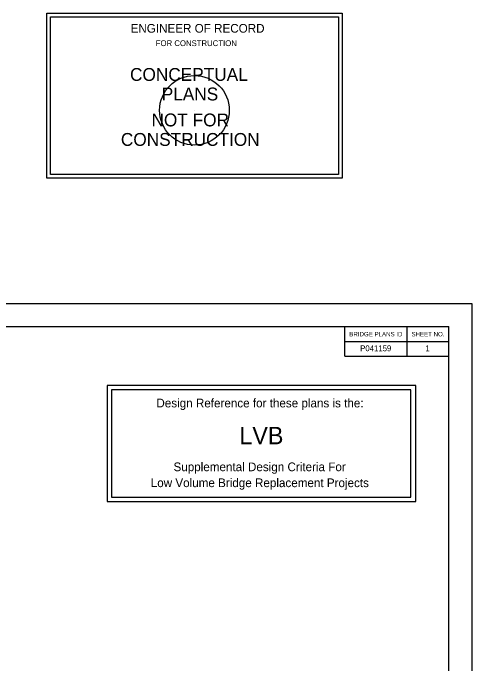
# Model space of a CAD drawing. Extents: x 0 to 4.05, y -2.5 to 2.32.
# Drawn here: x 2.177 to 3, y -1.314 to -0.145 of the extents above; entities that cross this region are included whole.
import ezdxf

# ---------------------------------------------------------------- set-up
doc = ezdxf.new("R2010")
doc.units = 0
for name, color, linetype in [('BR_AUTO DIMENSION', 7, 'Continuous'), ('BR_BORDER LINES', 7, 'Continuous'), ('BR_DETAILS', 7, 'Continuous'), ('Default', 7, 'Continuous'), ('NoPlot', 7, 'Continuous')]:
    doc.layers.add(name, color=color, linetype=linetype)

msp = doc.modelspace()

# ---------------------------------------------------------------- linework, layer by layer
at = {"layer": 'BR_AUTO DIMENSION'}
for points in [[(2.3457, -1.0225), (2.8996, -1.0225), (2.8996, -0.8141), (2.3457, -0.8141)], [(2.3535, -1.0146), (2.8902, -1.0146), (2.8902, -0.8219), (2.3535, -0.8219)]]:
    msp.add_lwpolyline(points, close=True, dxfattribs=at)
at = {"layer": 'BR_BORDER LINES'}
for p, q in [((0.1667, -0.7082), (2.9583, -0.7082)), ((2.7722, -0.7614), (2.7722, -0.7083)), ((2.8837, -0.7614), (2.8837, -0.7083)), ((2.9583, -2.4582), (2.9583, -0.7082)), ((2.7722, -0.7349), (2.9583, -0.7349)), ((2.7722, -0.7614), (2.9583, -0.7614)), ((2.9583, -1.3928), (2.9583, -0.8053))]:
    msp.add_line(p, q, dxfattribs=at)
at = {"layer": 'BR_DETAILS'}
for points in [[(2.2372, -0.1449), (2.7672, -0.1449), (2.7672, -0.4415), (2.2372, -0.4415)], [(2.2439, -0.1515), (2.7606, -0.1515), (2.7606, -0.4349), (2.2439, -0.4349)]]:
    msp.add_lwpolyline(points, close=True, dxfattribs=at)
at = {"layer": 'Default'}
msp.add_line((2.921, -0.7481), (2.921, -0.7481), dxfattribs=at)
at = {"layer": 'NoPlot'}
msp.add_line((2.5022, -0.3196), (2.5022, -0.3196), dxfattribs=at)
msp.add_lwpolyline([(0, -0.6667), (3, -0.6667), (3, -2.5), (0, -2.5)], close=True, dxfattribs=at)
msp.add_circle((2.5022, -0.3196), 0.0625, dxfattribs=at)

# ---------------------------------------------------------------- texts
at = {"layer": 'BR_AUTO DIMENSION'}
for s, height, p in [('P041159', 0.01042, (2.7995, -0.7523)), ('1', 0.0104, (2.9163, -0.7523)), ('Design Reference for these plans is the:', 0.015625, (2.4339, -0.8532)), ('LVB', 0.03125, (2.5828, -0.9194)), ('Supplemental Design Criteria For', 0.015625, (2.4646, -0.9678)), ('Low Volume Bridge Replacement Projects', 0.015625, (2.4238, -0.9964))]:
    msp.add_text(s, height=height, dxfattribs=at).set_placement(p)
at = {"layer": 'BR_DETAILS'}
for s, height, p in [('CONCEPTUAL', 0.02311, (2.3866, -0.2668)), ('PLANS', 0.02311, (2.4435, -0.3019)), ('NOT FOR', 0.02311, (2.4251, -0.3485)), ('CONSTRUCTION', 0.023108, (2.3702, -0.3835)), ('BRIDGE PLANS ID', 0.007961, (2.78, -0.7256)), ('SHEET NO.', 0.00796, (2.8915, -0.7256))]:
    msp.add_text(s, height=height, rotation=360, dxfattribs=at).set_placement(p)
at = {"layer": 'Default'}
for s, height, p in [('ENGINEER OF RECORD', 0.015625, (2.3876, -0.1802)), ('FOR CONSTRUCTION', 0.010417, (2.4328, -0.2043))]:
    msp.add_text(s, height=height, dxfattribs=at).set_placement(p)

doc.saveas('drawing.dxf')
